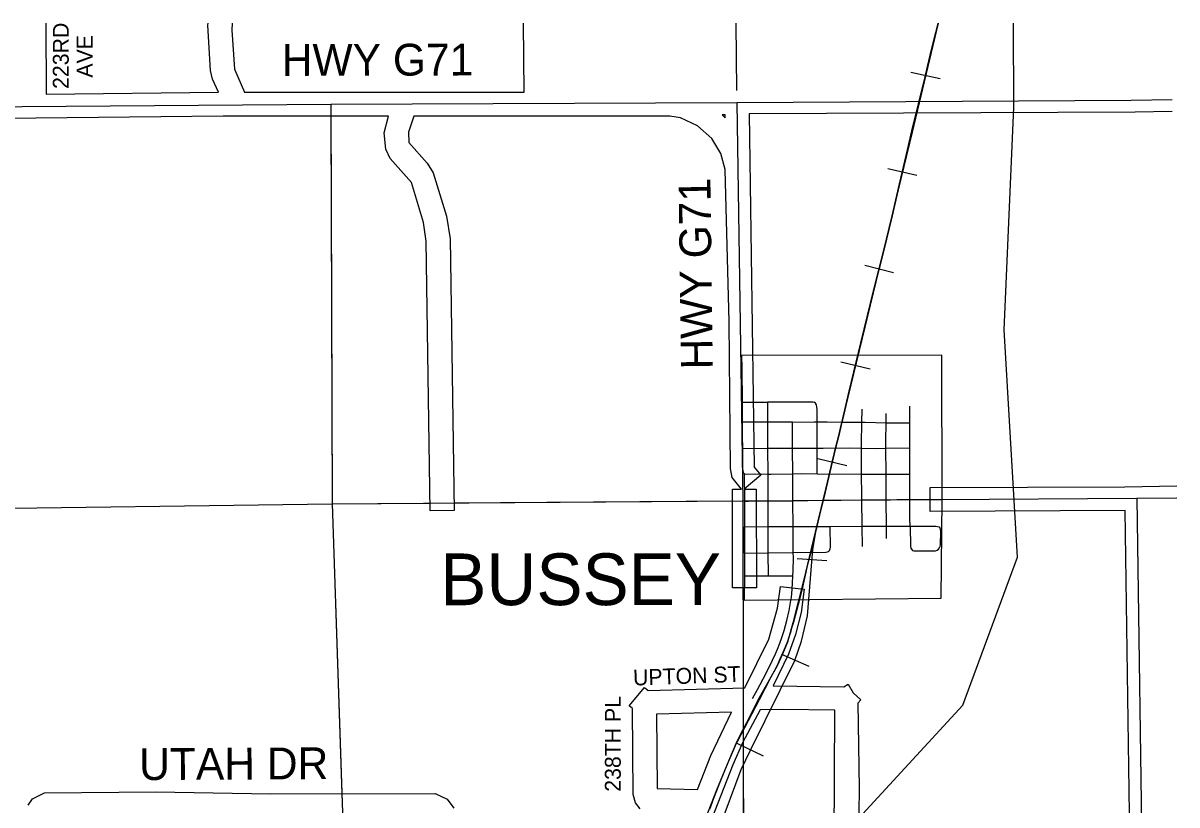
# Model space of a CAD drawing. Extents: x 10133 to 81668, y 5524 to 11018.
# Drawn here: x 23374.6 to 23737.1, y 8582 to 8827.6 of the extents above; entities that cross this region are included whole.
import ezdxf

# ---------------------------------------------------------------- set-up
doc = ezdxf.new("R2010")
doc.units = 0
doc.layers.add('Default', color=7, linetype='Continuous')

msp = doc.modelspace()

# ---------------------------------------------------------------- linework, layer by layer
at = {"layer": 'Default'}
for p, q in [((23662.64, 8810.15), (23653.49, 8812.16)), ((23655.36, 8779.72), (23646.22, 8781.81)), ((23648.06, 8749.21), (23638.98, 8751.53)), ((23640.64, 8718.92), (23631.52, 8721.11)), ((23633.32, 8688.53), (23624.21, 8690.75)), ((23627.12, 8658.68), (23617.77, 8659.33)), ((23621.54, 8625.48), (23612.95, 8629.25)), ((23607.13, 8597.31), (23598.71, 8601.44))]:
    msp.add_line(p, q, dxfattribs=at)
for points in [[(23381.7, 8827.64), (23381.86, 8805.3), (23436.02, 8805.9), (23434.04, 8810.05), (23433.42, 8812.71), (23432.61, 8827.02), (23432.71, 8827.64)], [(23440.3, 8827.64), (23440.12, 8825.39), (23440.95, 8813.17), (23444.1, 8805.9), (23532.02, 8805.91)], [(23531.13, 8289.64), (23545.83, 8370.55), (23563.76, 8458.5), (23578.67, 8496.18), (23617.68, 8556.69), (23669.83, 8613.4), (23686.99, 8659.87), (23682.82, 8731.27), (23685.84, 8801.15), (23685.67, 8827.64)], [(23532.02, 8805.91), (23531.82, 8827.64)], [(23662.07, 8827.64), (23653.87, 8793.33), (23625.83, 8677.74), (23619.8, 8652.4), (23616.36, 8639.24), (23614.67, 8633.19), (23613.14, 8629.36), (23611.38, 8625.54), (23605.87, 8615.67), (23601.89, 8607.85), (23599.9, 8604.02), (23598.52, 8601.27), (23596.15, 8595.76), (23592.4, 8586.65), (23549.3, 8476.19)], [(23662.1, 8827.64), (23661.32, 8824.69), (23660, 8819.33), (23658.68, 8813.97), (23657.98, 8810.77), (23655.86, 8802.3), (23653.74, 8793.84), (23652.4, 8787.78), (23651.18, 8782.44), (23649.95, 8777.11), (23647.58, 8767.13), (23644.93, 8755.89), (23641.87, 8743.9), (23637.8, 8727.17), (23634.14, 8711.96), (23633.07, 8707.5), (23632, 8703.03), (23631.61, 8701.37), (23630.81, 8698.04), (23629.84, 8694.06), (23628.87, 8690.09), (23628.44, 8688.31), (23627.33, 8683.46), (23626.11, 8678.45), (23624.81, 8673.07), (23623.87, 8669.07), (23622.99, 8665.38), (23622, 8661.37), (23621.05, 8657.58), (23620.09, 8653.29), (23619.28, 8649.91), (23618.47, 8646.54), (23617.51, 8643), (23616.56, 8639.46), (23616.12, 8637.84), (23615.68, 8636.22), (23615.18, 8634.77), (23614.69, 8633.32), (23613.96, 8631.61), (23613.24, 8629.89), (23612.34, 8627.84), (23611.44, 8625.78), (23610.53, 8624.06), (23609.63, 8622.35), (23607.58, 8618.54), (23605.82, 8615.03), (23602.38, 8608.44), (23598.94, 8601.85), (23598.33, 8600.61), (23597.72, 8599.36), (23596.31, 8596.03), (23594.9, 8592.71), (23593.2, 8588.36), (23591.5, 8584.02), (23590.17, 8580.64)], [(23591.77, 8570.62), (23600.19, 8593.14), (23603.09, 8599.27), (23617.04, 8627.44), (23619.17, 8633.42), (23621, 8641.47), (23622.7, 8662.23), (23623.87, 8669.07), (23624.81, 8673.07), (23626.11, 8678.45), (23627.33, 8683.46), (23628.44, 8688.31), (23628.87, 8690.09), (23629.84, 8694.06), (23630.81, 8698.04), (23631.61, 8701.37), (23632, 8703.03), (23633.07, 8707.5), (23634.14, 8711.96), (23637.8, 8727.17), (23641.87, 8743.9), (23644.93, 8755.89), (23647.58, 8767.13), (23649.95, 8777.11), (23651.18, 8782.44), (23652.4, 8787.78), (23653.74, 8793.84), (23655.86, 8802.3), (23657.98, 8810.77), (23658.68, 8813.97), (23660, 8819.33), (23661.32, 8824.69), (23662.1, 8827.64)], [(23598.52, 8827.64), (23598.75, 8806.46)], [(23346.43, 8801.19), (23471.23, 8802.13)], [(23471.23, 8802.13), (23598.79, 8802.74)], [(23471.23, 8802.13), (23471.66, 8676.63)], [(23598.79, 8802.74), (23722.73, 8803.46)], [(23598.79, 8802.74), (23600.72, 8677.54)], [(23722.73, 8803.46), (23735.53, 8803.65)], [(23735.57, 8799.82), (23723.93, 8799.65), (23602.63, 8799.1), (23604.3, 8688.09), (23606.36, 8685.66), (23601.12, 8681.23), (23604.91, 8681.23), (23604.95, 8650.23), (23597.45, 8650.22), (23597.41, 8681.22), (23600.29, 8681.22), (23597.37, 8684.84), (23596.81, 8687.67), (23596.37, 8733.78), (23595.14, 8781.63), (23593.73, 8786.65), (23590.98, 8791.38), (23586.47, 8795.38), (23581.15, 8797.83), (23577.8, 8798.39), (23497.31, 8798.43), (23495.63, 8793.33), (23495.78, 8790.1), (23501.54, 8783.59), (23503.46, 8780.55), (23507.57, 8766.95), (23508.7, 8759.85), (23510, 8674.49), (23502.51, 8674.45), (23501.24, 8759.11), (23500.32, 8765.04), (23496.59, 8777.53), (23489.92, 8785.13), (23488.58, 8788.01), (23488.02, 8793.18), (23489.36, 8798.42), (23437.46, 8798.42), (23104.1, 8794.81)], [(23471.25, 8798.42), (23471.66, 8676.63)], [(23595.16, 8797.91), (23595.13, 8798.83), (23594.22, 8798.82), (23595.16, 8797.91)], [(23600.45, 8708.54), (23602.25, 8708.51), (23608.59, 8708.54)], [(23608.54, 8694.05), (23608.53, 8694.79), (23608.57, 8702.25), (23608.59, 8708.54)], [(23624.02, 8702.34), (23624.01, 8706.1), (23623.98, 8707.09), (23623.82, 8707.74), (23623.55, 8708.23), (23623.53, 8708.24), (23623.24, 8708.45), (23622.81, 8708.51), (23612.92, 8708.57), (23608.59, 8708.54)], [(23653.13, 8702.1), (23653.11, 8707.34)], [(23638.08, 8702.23), (23638.16, 8706.32)], [(23645.69, 8702.1), (23645.71, 8704.99)], [(23616.41, 8677.57), (23616.37, 8686.07), (23616.33, 8694.08), (23616.32, 8697.28), (23616.29, 8702.3), (23608.57, 8702.25), (23602.9, 8702.22), (23600.46, 8702.22)], [(23616.29, 8702.3), (23623.15, 8702.34), (23624.02, 8702.34)], [(23624.03, 8694.06), (23624.04, 8695.99), (23624.02, 8702.34)], [(23624.02, 8702.34), (23627.18, 8702.34), (23631.81, 8702.31), (23638.08, 8702.23)], [(23637.95, 8694.12), (23637.94, 8695.41), (23638.08, 8702.23)], [(23638.08, 8702.23), (23639.11, 8702.22), (23645.68, 8702.1), (23645.69, 8702.1)], [(23645.66, 8694.06), (23645.65, 8696.42), (23645.69, 8702.1)], [(23645.69, 8702.1), (23653.13, 8702.1)], [(23653.17, 8694.17), (23653.13, 8702.1)], [(23600.57, 8694.03), (23608.54, 8694.05)], [(23608.54, 8694.05), (23616.33, 8694.08), (23618.03, 8694.08), (23624.03, 8694.06)], [(23608.64, 8669.45), (23608.68, 8677.51), (23608.69, 8680.55), (23608.63, 8685.95), (23608.54, 8694.05)], [(23624.01, 8686.08), (23624.03, 8694.06)], [(23624.03, 8694.06), (23625.95, 8694.05), (23634.3, 8694.2), (23637.95, 8694.12)], [(23638, 8685.93), (23637.95, 8694.12)], [(23637.95, 8694.12), (23642.6, 8694.02), (23645.66, 8694.06)], [(23645.66, 8694.06), (23653.17, 8694.17)], [(23645.69, 8685.92), (23645.66, 8694.06)], [(23653.2, 8685.94), (23653.2, 8686.44), (23653.17, 8694.17)], [(23601.07, 8686.1), (23601.38, 8685.94), (23604.37, 8686), (23608.63, 8685.95), (23609.61, 8685.94), (23616.37, 8686.07), (23616.37, 8686.07)], [(23616.37, 8686.07), (23619.23, 8686.13), (23624.01, 8686.08)], [(23624.01, 8686.08), (23624.01, 8686.08), (23638, 8685.93)], [(23638.18, 8669.57), (23638.06, 8677.85), (23638.03, 8679.25), (23638, 8685.93)], [(23638, 8685.93), (23640.1, 8685.91), (23645.69, 8685.92)], [(23645.69, 8685.92), (23653.2, 8685.94)], [(23645.78, 8669.61), (23645.78, 8669.64), (23645.73, 8677.91), (23645.71, 8680.7), (23645.69, 8685.92)], [(23653.25, 8669.64), (23653.2, 8672.04), (23653.2, 8677.95), (23653.2, 8685.94)], [(23722.49, 8557.27), (23720.83, 8674.49), (23659.59, 8674.23), (23659.54, 8681.73), (23720.7, 8681.98), (23737.01, 8682.25)], [(23600.72, 8677.54), (23724.47, 8678.35)], [(23616.41, 8677.57), (23625.83, 8677.74), (23626.01, 8677.74), (23638.06, 8677.85), (23639.45, 8677.87), (23645.73, 8677.91), (23649.1, 8677.93), (23653.2, 8677.95), (23655.88, 8677.96), (23657.4, 8677.97), (23663.32, 8678.01)], [(23724.47, 8678.35), (23737.06, 8678.55)], [(23724.47, 8678.35), (23726.27, 8553.59)], [(23347.95, 8674.98), (23471.66, 8676.63)], [(23347.95, 8674.98), (23471.66, 8676.63)], [(23471.66, 8676.63), (23600.72, 8677.54)], [(23471.66, 8676.63), (23502.5, 8676.85)], [(23471.66, 8676.63), (23474.72, 8585.66)], [(23471.66, 8676.63), (23475.87, 8551.39)], [(23510, 8676.9), (23597.42, 8677.51)], [(23600.72, 8677.54), (23600.92, 8552.99)], [(23601.17, 8677.48), (23601.6, 8677.47), (23602.46, 8677.47), (23608.68, 8677.51), (23612.8, 8677.54), (23615.84, 8677.56), (23616.41, 8677.57)], [(23615.84, 8646.59), (23616.04, 8648.24), (23616.32, 8651.72), (23616.43, 8653.98), (23616.5, 8655.61), (23616.56, 8659.64), (23616.55, 8661.33), (23616.48, 8669.48), (23616.41, 8677.46), (23616.41, 8677.57)], [(23601.18, 8669.42), (23608.64, 8669.45), (23608.64, 8669.45)], [(23601.19, 8661.13), (23601.18, 8669.42)], [(23608.68, 8661.23), (23608.63, 8666.37), (23608.64, 8669.45)], [(23608.64, 8669.45), (23616.48, 8669.48), (23628.13, 8669.53), (23638.18, 8669.57)], [(23608.68, 8661.23), (23608.7, 8661.23), (23616.55, 8661.33), (23626.88, 8661.47), (23627.65, 8661.68), (23627.89, 8661.93), (23627.93, 8662), (23628.17, 8662.45), (23628.26, 8663.04), (23628.13, 8669.51)], [(23638.18, 8669.57), (23645.78, 8669.61)], [(23638.28, 8663.19), (23638.18, 8669.54), (23638.18, 8669.57)], [(23645.78, 8669.61), (23653.25, 8669.64), (23653.25, 8669.64)], [(23645.8, 8665.75), (23645.78, 8669.61)], [(23653.25, 8669.64), (23653.39, 8663.19), (23653.48, 8662.67), (23653.67, 8662.36), (23653.69, 8662.33), (23653.77, 8662.22), (23653.94, 8661.99), (23654.4, 8661.84), (23661.19, 8661.9), (23661.71, 8662.08), (23662.14, 8662.42), (23662.48, 8662.76), (23662.66, 8663.19), (23662.79, 8663.87), (23662.88, 8667.79), (23662.76, 8668.65), (23662.57, 8669.11)], [(23653.25, 8669.64), (23654.87, 8669.64), (23661.34, 8669.6), (23661.83, 8669.54), (23662.33, 8669.39), (23662.57, 8669.11)], [(23601.19, 8661.13), (23608.68, 8661.23)], [(23608.74, 8653.98), (23608.68, 8661.23)], [(23601.2, 8653.98), (23608.74, 8653.98), (23616.43, 8653.98)], [(23568.47, 8580.82), (23566.97, 8582.71), (23566.28, 8585.29), (23566.04, 8612.31), (23565, 8613.16), (23569.75, 8618.96), (23570.9, 8618.01), (23601.32, 8618.86), (23608.81, 8634.11), (23611.6, 8643.88), (23612.56, 8650.68), (23620, 8649.78), (23618.97, 8642.49), (23617.19, 8635.57), (23615.02, 8629.41), (23610.17, 8619.49), (23632.44, 8619.11), (23633.75, 8619.92), (23635.4, 8617.24), (23637.78, 8615.06), (23636.84, 8614.04), (23637.25, 8587.27), (23636.81, 8556.25)], [(23600.77, 8650.23), (23600.81, 8618.83)], [(23603.74, 8615.42), (23603.75, 8615.44), (23605.25, 8618.28), (23607.9, 8623.18), (23609.97, 8627.46), (23610.92, 8629.44), (23611.6, 8630.95), (23612.34, 8632.86), (23612.9, 8634.58), (23613.64, 8636.77), (23614.5, 8639.92), (23615.27, 8643.12), (23615.79, 8646.2), (23615.83, 8646.51)], [(23557.8, 8492.97), (23629.97, 8493.85), (23629.29, 8550.08), (23629.56, 8611.84), (23613.13, 8612.03), (23606.12, 8611.93), (23600.58, 8601.57), (23597.5, 8594.59), (23557.8, 8492.97)], [(23586.44, 8586.87), (23590.6, 8597.54), (23597.16, 8611.16), (23573.53, 8610.57), (23573.8, 8587.23), (23586.44, 8586.87)], [(23600.84, 8602.04), (23600.92, 8552.99)], [(23376.19, 8581.92), (23377.55, 8583.94), (23381.36, 8585.81), (23416.31, 8586.12), (23452.29, 8585.53), (23504.04, 8585.64), (23507.81, 8583.84), (23509.93, 8580.96)]]:
    msp.add_lwpolyline(points, dxfattribs=at)
msp.add_lwpolyline([(23663.22, 8723.27), (23600.27, 8723.24), (23600.33, 8719.12), (23600.45, 8708.54), (23600.45, 8704.14), (23600.46, 8702.22), (23600.48, 8697.88), (23600.57, 8693.96), (23600.55, 8687.85), (23600.64, 8686.93), (23600.75, 8686.46), (23601.07, 8686.1), (23601.17, 8677.48), (23601.18, 8669.42), (23601.19, 8661.13), (23601.2, 8653.98), (23601.11, 8646.36), (23662.96, 8646.98), (23663.32, 8678.01)], close=True, dxfattribs=at)

# ---------------------------------------------------------------- texts
for s, height, rotation, p in [('223RD', 5, 90, (23388.93, 8806.95)), ('AVE', 5, 90, (23396.43, 8810.5)), ('HWY G71', 10, 0.1271, (23455.85, 8811.05)), ('HWY G71', 10, 90.7299, (23591.26, 8718.88)), ('BUSSEY', 16.25, 0.0248, (23505.66, 8644.77)), ('UPTON ST', 5, 1.9743, (23566.28, 8619.52)), ('238TH PL', 5, 90, (23562.35, 8586.16)), ('UTAH DR', 10, 0.283, (23411.06, 8589.84))]:
    msp.add_text(s, height=height, rotation=rotation, dxfattribs=at).set_placement(p)

doc.saveas('drawing.dxf')
